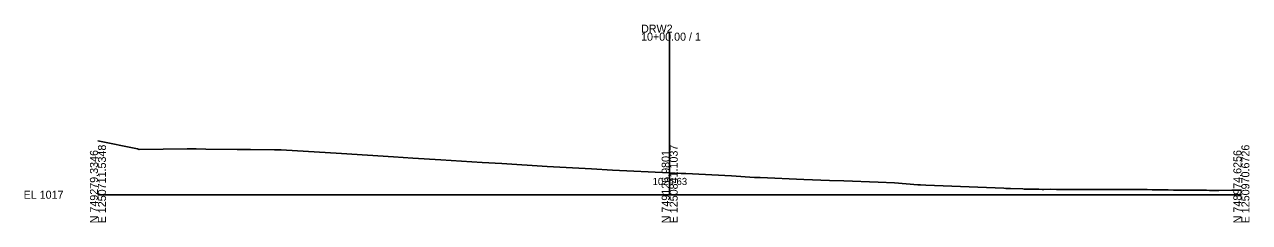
# Model space of a CAD drawing. Extents: x -26 to 403, y -366 to 1122.
# Drawn here: x -25.7 to 402.8, y -9.7 to 59.4 of the extents above; entities that cross this region are included whole.
import ezdxf

# ---------------------------------------------------------------- set-up
doc = ezdxf.new("R2010")
doc.units = 0
for name, color, linetype in [('Default', 7, 'Continuous'), ('Exist Cross Section Cell', 7, 'Continuous'), ('Exist XS Center Line Elevation Label', 7, 'Continuous'), ('Exist XS Ground Line', 7, 'Continuous')]:
    doc.layers.add(name, color=color, linetype=linetype)

msp = doc.modelspace()

# ---------------------------------------------------------------- linework, layer by layer
at = {"layer": 'Exist Cross Section Cell'}
for p, q in [((200, 0), (200, 56.6)), ((0, 0), (200, 0)), ((200, 0), (400, 0))]:
    msp.add_line(p, q, dxfattribs=at)
at = {"layer": 'Exist XS Ground Line'}
msp.add_lwpolyline([(0, 18.87), (13.88, 15.99), (14.46, 15.82), (31.24, 15.99), (34.36, 15.97), (37.76, 15.89), (48.7, 15.82), (53.41, 15.75), (61.76, 15.73), (62.51, 15.72), (64.04, 15.71), (85.23, 14.37), (103.44, 13.23), (110.12, 12.81), (119.98, 12.22), (134.46, 11.29), (141.25, 10.88), (157.19, 9.9), (172.65, 9.04), (179.97, 8.62), (200, 7.63), (204.06, 7.43), (204.37, 7.41), (205.62, 7.36), (221.67, 6.56), (229.73, 6.07), (231.66, 6.05), (246.99, 5.31), (255.86, 4.96), (260.91, 4.88), (272.95, 4.38), (278.65, 4.12), (286.87, 3.45), (287.7, 3.43), (289.65, 3.34), (316.94, 2.27), (317.57, 2.22), (319.28, 2.14), (323.59, 2), (323.96, 1.98), (327.6, 1.96), (328.28, 1.93), (329.12, 1.9), (330.29, 1.88), (330.86, 1.87), (333.36, 1.89), (335.36, 1.84), (337.01, 1.82), (338.36, 1.8), (341.32, 1.79), (350.11, 1.87), (364.22, 1.77), (367.08, 1.79), (368.84, 1.76), (369.57, 1.74), (370.47, 1.72), (371.55, 1.7), (372.86, 1.68), (374.44, 1.65), (376.31, 1.62), (378.49, 1.59), (386.62, 1.58), (387.04, 1.56), (387.75, 1.54), (388.81, 1.51), (390.29, 1.49), (392.06, 1.47), (396.7, 1.64), (400, 1.62)], dxfattribs=at)

# ---------------------------------------------------------------- texts
at = {"layer": 'Default'}
msp.add_text('-', height=0.0001, dxfattribs=at).set_placement((0, 0))
msp.add_text('-', height=0.0001, dxfattribs=at).set_placement((0, 0))
at = {"layer": 'Exist Cross Section Cell'}
for s, p in [('10+00.00 / 1', (190, 53.8)), ('DRW2', (190, 56.6)), ('EL 1017', (-26, -1.4))]:
    msp.add_text(s, height=2.8, dxfattribs=at).set_placement(p)
for s, p in [('E 1250711.5348', (2.8, -10)), ('E 1250841.1037', (202.8, -10)), ('E 1250970.6726', (402.8, -10)), ('N 749279.3346', (0, -10)), ('N 749126.9801', (200, -10)), ('N 748974.6256', (400, -10))]:
    msp.add_text(s, height=2.8, rotation=90, dxfattribs=at).set_placement(p)
at = {"layer": 'Exist XS Center Line Elevation Label'}
msp.add_text('1024.63', height=2.5, dxfattribs=at).set_placement((194.03, 3.38))

doc.saveas('drawing.dxf')
